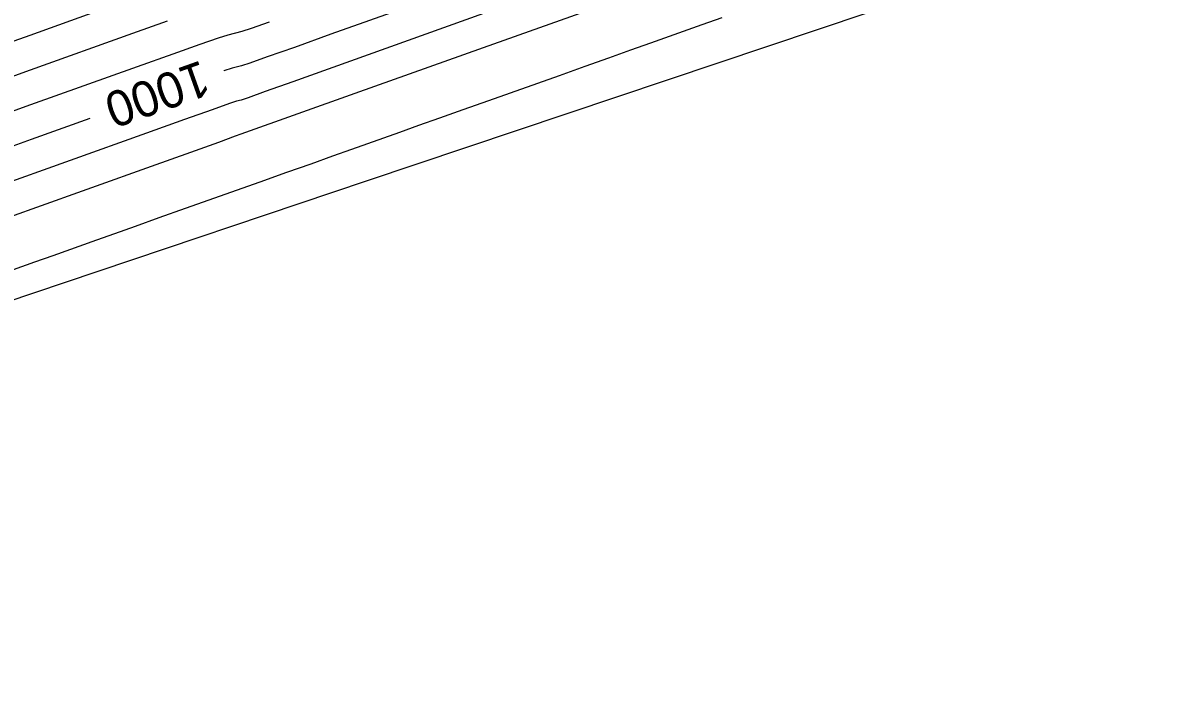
# Model space of a CAD drawing. Extents: x 2175772 to 2185556, y 721391 to 722853.
# Drawn here: x 2179071.3 to 2179161.1, y 721866 to 721918.3 of the extents above; entities that cross this region are included whole.
import ezdxf

# ---------------------------------------------------------------- set-up
doc = ezdxf.new("R2010")
doc.units = 0
for name, color, linetype in [('DT_X_Contour_Major', 7, 'Continuous'), ('DT_X_Contour_Minor', 7, 'Continuous'), ('DT_X_TIN_Hull', 7, 'Continuous')]:
    doc.layers.add(name, color=color, linetype=linetype)

msp = doc.modelspace()

# ---------------------------------------------------------------- linework, layer by layer
at = {"layer": 'DT_X_Contour_Major'}
for points in [[(2179104.223, 721920.477), (2179095.561, 721917.376), (2179092.684, 721916.349), (2179090.55, 721915.594), (2179089.16, 721915.111), (2179088.512, 721914.9), (2179087.776, 721914.701), (2179087.126, 721914.489), (2179087.125, 721914.489)], [(2179076.571, 721910.738), (2179071.948, 721909.083), (2179069.052, 721908.049)]]:
    msp.add_lwpolyline(points, dxfattribs=at)
at = {"layer": 'DT_X_Contour_Minor'}
for points in [[(2179181.624, 721942.699), (2179160.992, 721935.351), (2179137.395, 721926.947), (2179107.533, 721916.311), (2179097.444, 721912.717), (2179088.467, 721909.504), (2179088.025, 721909.346), (2179086.702, 721908.872), (2179084.498, 721908.083), (2179081.414, 721906.979), (2179072.013, 721903.615), (2179068.928, 721902.51)], [(2179079.572, 721920.051), (2179071.849, 721917.286), (2179069.238, 721916.358)], [(2179107.557, 721919.003), (2179092.563, 721913.638), (2179090.393, 721912.865), (2179089.036, 721912.387), (2179088.491, 721912.202), (2179088.121, 721912.102), (2179087.575, 721911.917), (2179086.214, 721911.437), (2179084.037, 721910.663), (2179081.045, 721909.594), (2179068.99, 721905.28)], [(2179090.707, 721918.323), (2179089.283, 721917.835), (2179088.533, 721917.598), (2179087.431, 721917.299), (2179086.676, 721917.061), (2179085.237, 721916.568), (2179083.115, 721915.822), (2179080.309, 721914.822), (2179071.915, 721911.818), (2179069.114, 721910.819)], [(2179082.654, 721918.401), (2179079.941, 721917.436), (2179071.882, 721914.552), (2179069.176, 721913.588)], [(2179126.332, 721918.678), (2179124.759, 721918.118), (2179120.725, 721916.681), (2179119.14, 721916.117), (2179117.411, 721915.502), (2179115.539, 721914.836), (2179113.522, 721914.12), (2179107.953, 721912.142), (2179105.95, 721911.43), (2179104.115, 721910.778), (2179102.449, 721910.185), (2179100.953, 721909.653), (2179097.188, 721908.311), (2179095.677, 721907.774), (2179093.97, 721907.166), (2179092.065, 721906.489), (2179089.963, 721905.743), (2179084.094, 721903.658), (2179082.007, 721902.917), (2179080.146, 721902.256), (2179078.512, 721901.675), (2179077.105, 721901.173), (2179073.654, 721899.944), (2179072.23, 721899.437), (2179070.546, 721898.838)]]:
    msp.add_lwpolyline(points, dxfattribs=at)
at = {"layer": 'DT_X_TIN_Hull'}
msp.add_lwpolyline([(2178979.881, 721865.982), (2179003.576, 721873.952), (2179027.271, 721881.923), (2179050.967, 721889.893), (2179074.662, 721897.864), (2179098.357, 721905.834), (2179122.052, 721913.804), (2179145.747, 721921.775), (2179169.442, 721929.745)], dxfattribs=at)

# ---------------------------------------------------------------- texts
at = {"layer": 'DT_X_Contour_Major'}
msp.add_text('1000', height=2.8, rotation=199.56363, dxfattribs=at).set_placement((2179085.363, 721915.361))

doc.saveas('drawing.dxf')
